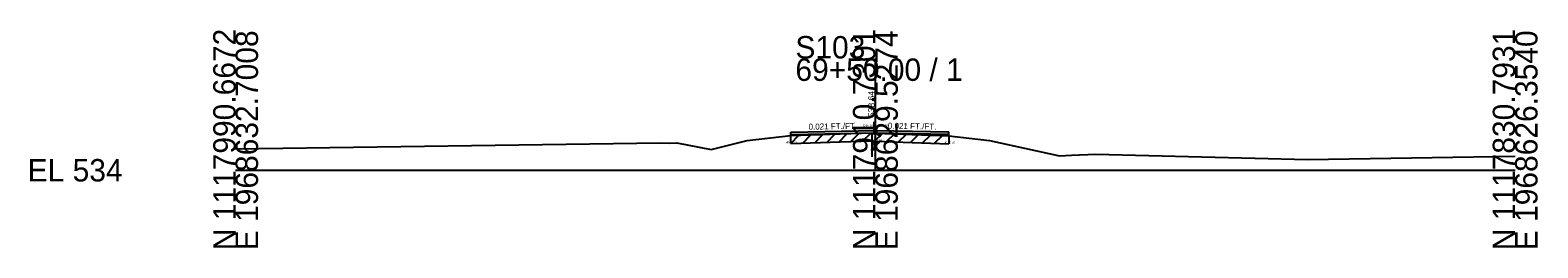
# Model space of a CAD drawing. Extents: x -26 to 163, y -10 to 24018.
# Drawn here: x -25.7 to 162.8, y 17490.3 to 17517.5 of the extents above; entities that cross this region are included whole.
import ezdxf

# ---------------------------------------------------------------- set-up
doc = ezdxf.new("R2010")
doc.units = 0
for name, color, linetype in [('RD_GPK_XS_Cell', 7, 'Continuous'), ('RD_XS_ExGround', 7, 'Continuous'), ('RD_XS_ExPaveRet', 7, 'Continuous'), ('RD_XS_Misc_Line', 7, 'Continuous'), ('RD_XS_PaveOvlay_CP', 7, 'Continuous'), ('RD_XS_TX_Elev_EX', 7, 'Continuous'), ('RD_XS_TX_ExEOP', 7, 'Continuous'), ('RD_XS_TX_Notes', 7, 'Continuous'), ('RD_XS_TX_Profile', 7, 'Continuous'), ('RD_XS_TX_Slope', 7, 'Continuous')]:
    doc.layers.add(name, color=color, linetype=linetype)

msp = doc.modelspace()

# ---------------------------------------------------------------- linework, layer by layer
at = {"layer": 'RD_GPK_XS_Cell'}
for p, q in [((80, 17500), (80, 17513.97)), ((0, 17500), (80, 17500)), ((80, 17500), (160, 17500))]:
    msp.add_line(p, q, dxfattribs=at)
at = {"layer": 'RD_XS_ExGround'}
msp.add_lwpolyline([(0, 17502.66), (53.11, 17503.41), (54.25, 17503.4), (55.18, 17503.44), (59.48, 17502.58), (63.96, 17503.71), (69.41, 17504.35), (75.58, 17504.54), (79.56, 17504.66), (80, 17504.64), (89.19, 17504.32), (94.28, 17503.7), (103.03, 17501.81), (104.53, 17501.88), (107.58, 17502.03), (134.07, 17501.35), (160, 17501.75)], dxfattribs=at)
at = {"layer": 'RD_XS_ExPaveRet'}
for p, q in [((69.41, 17503.35), (70.44, 17504.38)), ((69.41, 17503.35), (69.41, 17504.35)), ((69.41, 17503.35), (75.58, 17503.54)), ((70.91, 17503.4), (71.94, 17504.43)), ((72.41, 17503.44), (73.44, 17504.47)), ((73.91, 17503.49), (74.94, 17504.52)), ((75.41, 17503.53), (76.44, 17504.56)), ((75.58, 17503.54), (79.56, 17503.66)), ((76.91, 17503.58), (77.94, 17504.61)), ((78.41, 17503.62), (79.44, 17504.65)), ((79.56, 17503.66), (80, 17503.64)), ((79.91, 17503.64), (80.88, 17504.61)), ((80, 17503.64), (89.19, 17503.32)), ((81.41, 17503.59), (82.38, 17504.56)), ((82.91, 17503.54), (83.88, 17504.51)), ((84.41, 17503.49), (85.38, 17504.45)), ((85.91, 17503.43), (86.88, 17504.4)), ((87.41, 17503.38), (88.38, 17504.35)), ((89.19, 17504.32), (89.19, 17503.32))]:
    msp.add_line(p, q, dxfattribs=at)
at = {"layer": 'RD_XS_Misc_Line'}
msp.add_line((79.56, 17504.66), (79.56, 17501.66), dxfattribs=at)
at = {"layer": 'RD_XS_PaveOvlay_CP'}
for p, q in [((69.41, 17504.77), (80, 17504.99)), ((69.41, 17504.35), (69.41, 17504.77)), ((80, 17504.64), (69.41, 17504.42)), ((80, 17504.99), (89.19, 17504.79)), ((89.19, 17504.45), (80, 17504.64)), ((89.19, 17504.32), (89.19, 17504.79))]:
    msp.add_line(p, q, dxfattribs=at)

# ---------------------------------------------------------------- texts
at = {"layer": 'RD_GPK_XS_Cell'}
for s, p in [('N 1117990.6672', (0, 17490)), ('E 1968632.7008', (2.8, 17490)), ('N 1117910.7301', (80, 17490)), ('E 1968629.5274', (82.8, 17490)), ('N 1117830.7931', (160, 17490)), ('E 1968626.3540', (162.8, 17490))]:
    msp.add_text(s, height=2.8, rotation=90, dxfattribs=at).set_placement(p)
for s, p in [('S103', (70, 17513.97)), ('69+50.00 / 1', (70, 17511.17)), ('EL 534', (-26, 17498.6))]:
    msp.add_text(s, height=2.8, dxfattribs=at).set_placement(p)
at = {"layer": 'RD_XS_TX_Elev_EX'}
msp.add_text('538.64', height=0.8, rotation=90, dxfattribs=at).set_placement((79.9, 17506.64))
at = {"layer": 'RD_XS_TX_ExEOP'}
for s, p in [('EOP-L', (69.36, 17504.77)), ('EOP-R', (89.14, 17504.79))]:
    msp.add_text(s, height=0.1, rotation=270, dxfattribs=at).set_placement(p)
at = {"layer": 'RD_XS_TX_Notes'}
for s, p in [('Elev. @CL = 538.99', (78.47, 17505.49)), (' dE= 0.41', (68.71, 17503.35)), (' dE= 0.34', (79.29, 17503.64)), (' dE= 0.47', (88.48, 17503.32))]:
    msp.add_text(s, height=0.25, dxfattribs=at).set_placement(p)
msp.add_text(' Min. Distance @CP = -0.02', height=0.25, rotation=270, dxfattribs=at).set_placement((79.81, 17505.75))
at = {"layer": 'RD_XS_TX_Profile'}
msp.add_text('CL', height=0.25, dxfattribs=at).set_placement((79.77, 17504.99))
at = {"layer": 'RD_XS_TX_Slope'}
for rotation, p in [(1.1916, (71.65, 17505.06)), (358.8084, (81.55, 17505.2))]:
    msp.add_text('0.021 FT./FT.', height=0.75, rotation=rotation, dxfattribs=at).set_placement(p)

doc.saveas('drawing.dxf')
